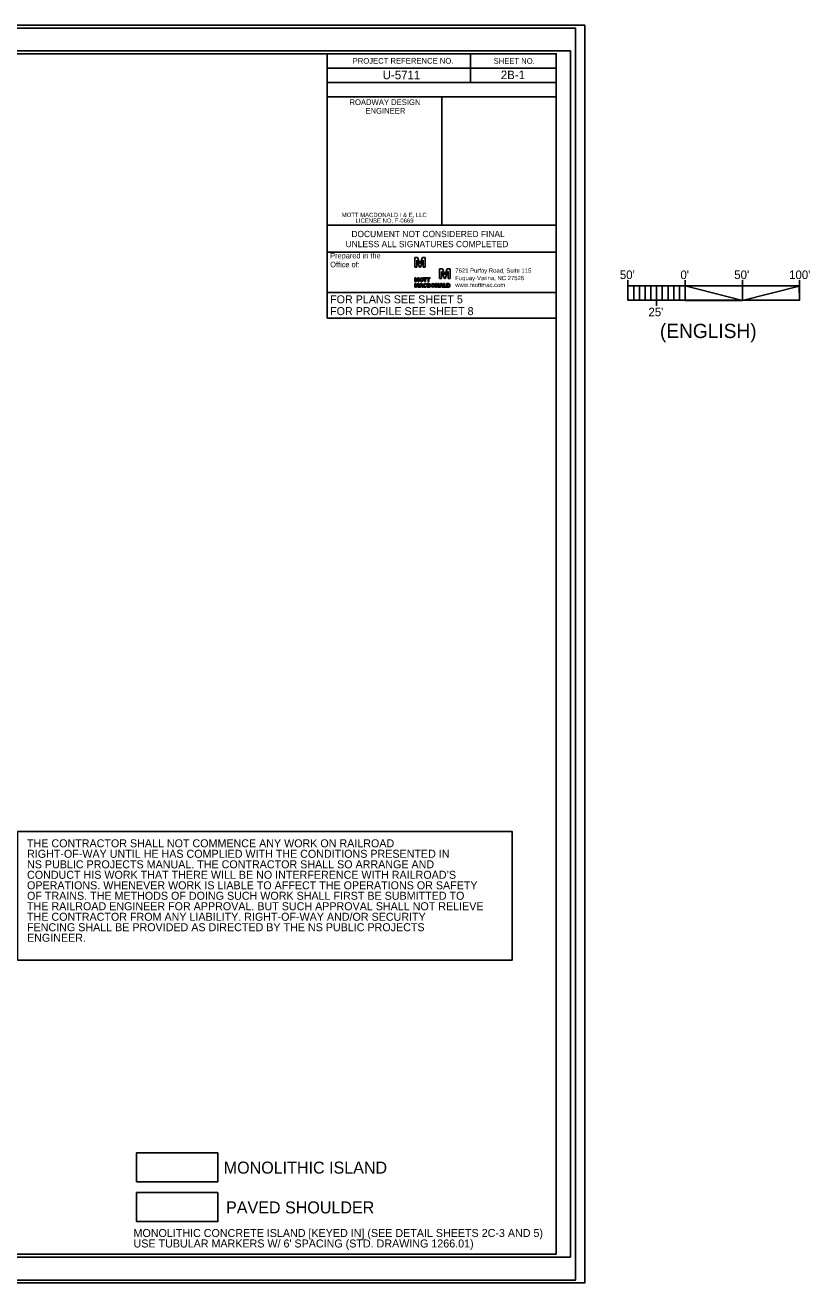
# Model space of a CAD drawing. Extents: x 1756964 to 1757438, y 736785 to 737067.
# Drawn here: x 1757266.4 to 1757437.8, y 736792 to 737067 of the extents above; entities that cross this region are included whole.
import ezdxf

# ---------------------------------------------------------------- set-up
doc = ezdxf.new("R2010")
doc.units = 0
for name, color, linetype in [('Old_Level_2', 7, 'Continuous'), ('Old_Level_40', 7, 'Continuous'), ('Old_Level_42', 7, 'Continuous'), ('Old_Level_45', 7, 'Continuous'), ('Old_Level_62', 7, 'Continuous'), ('Old_Level_63', 7, 'Continuous'), ('Prop Dimension', 7, 'Continuous'), ('Prop DSN Text', 7, 'Continuous'), ('Prop DSN White Annotation Label', 7, 'Continuous'), ('Prop PHM English Scale CELL', 7, 'Continuous'), ('Prop Shade Light', 7, 'Continuous'), ('Prop Shade Medium', 7, 'Continuous'), ('Sheet Data Field CELL', 7, 'Continuous'), ('Sheet Plan CELL', 7, 'Continuous'), ('Sheet Plot Border Inside CELL', 7, 'Continuous'), ('Sheet Plot Border Outside CELL', 7, 'Continuous'), ('Sheet Sticker Exception Certification CELL', 7, 'Continuous')]:
    doc.layers.add(name, color=color, linetype=linetype)

msp = doc.modelspace()

# ---------------------------------------------------------------- linework, layer by layer
at = {"layer": 'Old_Level_2'}
for p, q in [((1757352.13, 737016.21), (1757351.5, 737016.21)), ((1757351.5, 737016.21), (1757351.5, 737014.09)), ((1757351.95, 737014.09), (1757351.95, 737015.61)), ((1757351.95, 737015.61), (1757351.96, 737015.61)), ((1757351.96, 737015.61), (1757352.55, 737014.09)), ((1757352.64, 737014.9), (1757352.13, 737016.21)), ((1757352.64, 737014.88), (1757352.64, 737014.9)), ((1757352.66, 737014.88), (1757352.64, 737014.88)), ((1757353.17, 737016.21), (1757352.66, 737014.9)), ((1757352.66, 737014.9), (1757352.66, 737014.88)), ((1757352.75, 737014.09), (1757353.35, 737015.62)), ((1757353.8, 737016.21), (1757353.17, 737016.21)), ((1757353.35, 737015.62), (1757353.35, 737015.62)), ((1757353.35, 737015.62), (1757353.35, 737014.09)), ((1757353.8, 737014.09), (1757353.8, 737016.21)), ((1757351.5, 737014.09), (1757351.95, 737014.09)), ((1757352.55, 737014.09), (1757352.75, 737014.09)), ((1757353.35, 737014.09), (1757353.8, 737014.09)), ((1757357.53, 737013.74), (1757356.9, 737013.74)), ((1757356.9, 737013.74), (1757356.9, 737011.61)), ((1757357.35, 737011.61), (1757357.35, 737013.14)), ((1757357.35, 737013.14), (1757357.36, 737013.14)), ((1757357.36, 737013.14), (1757357.96, 737011.61)), ((1757358.05, 737012.42), (1757357.53, 737013.74)), ((1757358.05, 737012.4), (1757358.05, 737012.42)), ((1757358.06, 737012.4), (1757358.05, 737012.4)), ((1757358.57, 737013.74), (1757358.06, 737012.42)), ((1757358.06, 737012.42), (1757358.06, 737012.4)), ((1757358.15, 737011.61), (1757358.75, 737013.14)), ((1757359.2, 737013.74), (1757358.57, 737013.74)), ((1757358.75, 737013.14), (1757358.76, 737013.14)), ((1757358.76, 737013.14), (1757358.76, 737011.61)), ((1757359.2, 737011.61), (1757359.2, 737013.74)), ((1757351.74, 737011.76), (1757351.5, 737011.76)), ((1757351.5, 737011.76), (1757351.5, 737010.95)), ((1757351.5, 737010.95), (1757351.67, 737010.95)), ((1757351.74, 737010.5), (1757351.5, 737010.5)), ((1757351.5, 737010.5), (1757351.5, 737009.69)), ((1757351.5, 737009.69), (1757351.67, 737009.69)), ((1757351.67, 737010.95), (1757351.67, 737011.53)), ((1757351.67, 737011.53), (1757351.68, 737011.53)), ((1757351.67, 737011.53), (1757351.68, 737011.53)), ((1757351.67, 737009.69), (1757351.67, 737010.27)), ((1757351.67, 737010.27), (1757351.68, 737010.27)), ((1757351.68, 737011.53), (1757351.9, 737010.95)), ((1757351.68, 737010.27), (1757351.9, 737009.69)), ((1757351.94, 737011.25), (1757351.74, 737011.76)), ((1757351.94, 737009.99), (1757351.74, 737010.5)), ((1757351.9, 737010.95), (1757351.98, 737010.95)), ((1757351.9, 737009.69), (1757351.98, 737009.69)), ((1757352.14, 737011.76), (1757351.94, 737011.25)), ((1757352.14, 737010.5), (1757351.94, 737009.99)), ((1757351.98, 737010.95), (1757352.21, 737011.53)), ((1757351.98, 737009.69), (1757352.21, 737010.27)), ((1757352.38, 737011.76), (1757352.14, 737011.76)), ((1757352.38, 737010.5), (1757352.14, 737010.5)), ((1757352.21, 737011.53), (1757352.22, 737011.53)), ((1757352.21, 737011.53), (1757352.22, 737011.53)), ((1757352.21, 737011.53), (1757352.22, 737011.53)), ((1757352.21, 737010.27), (1757352.22, 737010.27)), ((1757352.22, 737011.53), (1757352.22, 737010.95)), ((1757352.22, 737010.95), (1757352.38, 737010.95)), ((1757352.22, 737010.27), (1757352.22, 737009.69)), ((1757352.22, 737009.69), (1757352.38, 737009.69)), ((1757352.38, 737010.95), (1757352.38, 737011.76)), ((1757352.38, 737010.95), (1757352.38, 737011.76)), ((1757352.38, 737009.69), (1757352.38, 737010.5)), ((1757354.09, 737009.85), (1757353.95, 737009.92)), ((1757354.09, 737009.85), (1757353.95, 737009.92)), ((1757353.97, 737010.23), (1757354.11, 737010.3)), ((1757353.97, 737010.23), (1757354.11, 737010.3)), ((1757354.59, 737010.5), (1757354.22, 737010.5)), ((1757354.22, 737010.5), (1757354.22, 737010.08)), ((1757354.22, 737010.08), (1757354.22, 737009.69)), ((1757354.22, 737009.69), (1757354.59, 737009.69)), ((1757354.39, 737009.84), (1757354.39, 737010.35)), ((1757354.39, 737010.35), (1757354.59, 737010.35)), ((1757354.59, 737009.84), (1757354.39, 737009.84)), ((1757356.9, 737011.61), (1757357.35, 737011.61)), ((1757357.96, 737011.61), (1757358.15, 737011.61)), ((1757358.43, 737010.5), (1757358.43, 737010.5)), ((1757358.8, 737010.5), (1757358.43, 737010.5)), ((1757358.43, 737010.5), (1757358.43, 737010.08)), ((1757358.43, 737010.08), (1757358.43, 737009.69)), ((1757358.43, 737009.69), (1757358.8, 737009.69)), ((1757358.6, 737009.84), (1757358.6, 737010.35)), ((1757358.6, 737010.35), (1757358.8, 737010.35)), ((1757358.8, 737009.84), (1757358.6, 737009.84)), ((1757358.76, 737011.61), (1757359.2, 737011.61)), ((1757358.8, 737010.34), (1757358.8, 737010.34))]:
    msp.add_line(p, q, dxfattribs=at)
for points in [[(1757352.48, 737009.69), (1757352.68, 737009.69), (1757352.73, 737009.82), (1757353.08, 737009.82), (1757353.13, 737009.69), (1757353.32, 737009.69), (1757353.01, 737010.5), (1757352.79, 737010.5), (1757352.48, 737009.69)], [(1757352.77, 737009.97), (1757352.9, 737010.32), (1757353.03, 737009.97), (1757352.77, 737009.97)], [(1757353.4, 737011.61), (1757353.64, 737011.61), (1757353.64, 737010.95), (1757353.81, 737010.95), (1757353.81, 737011.61), (1757354.05, 737011.61), (1757354.05, 737011.76), (1757353.4, 737011.76), (1757353.4, 737011.61)], [(1757354.15, 737011.61), (1757354.39, 737011.61), (1757354.39, 737010.95), (1757354.56, 737010.95), (1757354.56, 737011.61), (1757354.79, 737011.61), (1757354.79, 737011.76), (1757354.15, 737011.76), (1757354.15, 737011.61)], [(1757356.21, 737010.21), (1757356.22, 737010.21), (1757356.61, 737009.69), (1757356.77, 737009.69), (1757356.77, 737010.5), (1757356.6, 737010.5), (1757356.6, 737009.99), (1757356.22, 737010.5), (1757356.05, 737010.5), (1757356.05, 737009.69), (1757356.21, 737009.69), (1757356.21, 737010.21)], [(1757356.87, 737009.69), (1757357.07, 737009.69), (1757357.12, 737009.82), (1757357.47, 737009.82), (1757357.52, 737009.69), (1757357.71, 737009.69), (1757357.4, 737010.5), (1757357.19, 737010.5), (1757356.87, 737009.69)], [(1757357.17, 737009.97), (1757357.3, 737010.32), (1757357.43, 737009.97), (1757357.17, 737009.97)], [(1757358.33, 737009.69), (1757358.33, 737009.83), (1757357.98, 737009.83), (1757357.98, 737010.5), (1757357.81, 737010.5), (1757357.81, 737009.69), (1757358.33, 737009.69)], [(1757358.33, 737009.69), (1757358.33, 737009.83), (1757357.98, 737009.83), (1757357.98, 737010.5), (1757357.81, 737010.5), (1757357.81, 737009.69), (1757358.33, 737009.69), (1757358.33, 737009.83)]]:
    msp.add_lwpolyline(points, dxfattribs=at)
msp.add_arc((1757358.8, 737010.09), 0.406, 270, 90, dxfattribs=at)
for centre, major_axis, ratio in [((1757352.94, 737011.35), (0, 0.406), 0.993118), ((1757352.94, 737011.35), (0, 0.265), 0.916103), ((1757355.5, 737010.09), (0, 0.406), 0.993118), ((1757355.5, 737010.09), (0, 0.265), 0.916103)]:
    msp.add_ellipse(centre, major_axis=major_axis, ratio=ratio, dxfattribs=at)
for centre, major_axis, ratio, start_param, end_param in [((1757353.76, 737010.09), (0, 0.406), 0.993118, 5.246647, 10.366427), ((1757353.76, 737010.09), (0, 0.406), 0.993118, 5.246647, 10.366427), ((1757353.76, 737010.09), (0, 0.265), 0.916103, 5.276876, 9.424778), ((1757353.76, 737010.09), (0, 0.265), 0.916103, 5.276876, 10.296021), ((1757353.76, 737010.09), (0, 0.265), 0.916103, 3.141593, 4.012835), ((1757354.59, 737010.09), (0, -0.406), 0.930276, 0, 3.141593), ((1757354.59, 737010.1), (0, -0.253), 0.900832, 0, 3.141593), ((1757358.8, 737010.1), (0, -0.253), 0.900832, 0, 3.141593)]:
    msp.add_ellipse(centre, major_axis=major_axis, ratio=ratio, start_param=start_param, end_param=end_param, dxfattribs=at)
at = {"layer": 'Old_Level_40'}
for points in [[(1757308.47, 736820.45), (1757290.72, 736820.45), (1757290.72, 736814.1), (1757308.47, 736814.1)], [(1757308.47, 736811.75), (1757290.72, 736811.75), (1757290.72, 736805.4), (1757308.47, 736805.4)]]:
    msp.add_lwpolyline(points, close=True, dxfattribs=at)
at = {"layer": 'Old_Level_42'}
msp.add_lwpolyline([(1757382.4, 737008.54), (1757332.39, 737008.54), (1757332.39, 737017.36)], dxfattribs=at)
at = {"layer": 'Old_Level_62'}
msp.add_lwpolyline([(1756969.89, 736798.25), (1757382.39, 736798.25), (1757382.39, 737060.75), (1756969.89, 737060.75)], close=True, dxfattribs=at)
at = {"layer": 'Old_Level_63'}
msp.add_lwpolyline([(1757388.64, 737067), (1756963.64, 737067), (1756963.64, 736792), (1757388.64, 736792)], close=True, dxfattribs=at)
at = {"layer": 'Prop DSN Text'}
msp.add_lwpolyline([(1757332.39, 737008.54), (1757382.4, 737008.54), (1757382.4, 737002.92), (1757332.39, 737002.92)], close=True, dxfattribs=at)
at = {"layer": 'Prop DSN White Annotation Label'}
msp.add_lwpolyline([(1757264.72, 736890.67), (1757372.78, 736890.67), (1757372.78, 736862.56), (1757264.72, 736862.56)], close=True, dxfattribs=at)
at = {"layer": 'Prop PHM English Scale CELL'}
for p, q in [((1757398.08, 737011.48), (1757398.08, 737011.48)), ((1757398.08, 737011.23), (1757398.08, 737006.85)), ((1757435.58, 737009.98), (1757398.08, 737009.98)), ((1757398.08, 737009.98), (1757398.08, 737006.85)), ((1757404.33, 737009.98), (1757404.33, 737005.6)), ((1757410.58, 737011.23), (1757410.58, 737006.83)), ((1757423.08, 737011.48), (1757423.08, 737011.48)), ((1757423.08, 737011.23), (1757423.08, 737006.85)), ((1757435.58, 737011.48), (1757435.58, 737011.48)), ((1757435.58, 737011.23), (1757435.58, 737006.85)), ((1757435.58, 737006.85), (1757435.58, 737009.98)), ((1757398.08, 737006.85), (1757435.58, 737006.85))]:
    msp.add_line(p, q, dxfattribs=at)
for points in [[(1757399.33, 737009.98), (1757398.08, 737009.98), (1757398.08, 737006.85), (1757399.33, 737006.85)], [(1757400.58, 737009.98), (1757401.83, 737009.98), (1757401.83, 737006.85), (1757400.58, 737006.85)], [(1757403.08, 737009.98), (1757404.33, 737009.98), (1757404.33, 737006.85), (1757403.08, 737006.85)], [(1757405.58, 737009.98), (1757406.83, 737009.98), (1757406.83, 737006.85), (1757405.58, 737006.85)], [(1757408.08, 737009.98), (1757409.33, 737009.98), (1757409.33, 737006.85), (1757408.08, 737006.85)], [(1757410.58, 737009.98), (1757423.08, 737006.83), (1757410.58, 737006.83)], [(1757423.08, 737006.83), (1757435.52, 737009.93), (1757435.58, 737006.85)]]:
    msp.add_lwpolyline(points, close=True, dxfattribs=at)
at = {"layer": 'Prop Shade Light'}
msp.add_lwpolyline([(1757308.47, 736811.75), (1757290.72, 736811.75), (1757290.72, 736805.4), (1757308.47, 736805.4), (1757308.47, 736811.75)], dxfattribs=at)
at = {"layer": 'Prop Shade Medium'}
msp.add_lwpolyline([(1757308.47, 736820.45), (1757290.72, 736820.45), (1757290.72, 736814.1), (1757308.47, 736814.1), (1757308.47, 736820.45)], dxfattribs=at)
at = {"layer": 'Sheet Plan CELL'}
for p, q in [((1757363.64, 737060.73), (1757363.65, 737054.48)), ((1757332.38, 737057.61), (1757382.39, 737057.61)), ((1757332.38, 737054.48), (1757382.39, 737054.49)), ((1757332.38, 737054.48), (1757332.38, 737051.36)), ((1757357.39, 737051.36), (1757357.4, 737023.24))]:
    msp.add_line(p, q, dxfattribs=at)
for points in [[(1757382.4, 737060.75), (1757007.39, 737060.75), (1757007.39, 736798.25), (1757382.39, 736798.25)], [(1757332.38, 737060.75), (1757382.4, 737060.75), (1757382.39, 737054.49), (1757332.38, 737054.48)], [(1757332.38, 737051.36), (1757357.39, 737051.36), (1757357.39, 737023.23), (1757332.39, 737023.24)], [(1757357.39, 737051.36), (1757382.39, 737051.36), (1757382.39, 737023.23), (1757357.39, 737023.23)]]:
    msp.add_lwpolyline(points, close=True, dxfattribs=at)
at = {"layer": 'Sheet Plot Border Inside CELL'}
msp.add_lwpolyline([(1756969.02, 736797.62), (1757385.52, 736797.62), (1757385.52, 737061.37), (1756969.02, 737061.37)], close=True, dxfattribs=at)
at = {"layer": 'Sheet Plot Border Outside CELL'}
msp.add_lwpolyline([(1756965.77, 736792.62), (1757386.64, 736792.62), (1757386.64, 737066.37), (1756965.77, 737066.37)], close=True, dxfattribs=at)
at = {"layer": 'Sheet Sticker Exception Certification CELL'}
for p, q in [((1757332.39, 737017.36), (1757332.39, 737023.24)), ((1757332.39, 737023.24), (1757382.39, 737023.24)), ((1757382.39, 737023.23), (1757382.39, 737017.36)), ((1757382.39, 737017.36), (1757332.39, 737017.36))]:
    msp.add_line(p, q, dxfattribs=at)

# ---------------------------------------------------------------- texts
at = {"layer": 'Old_Level_2'}
for s, height, p in [('Office of:', 1.205, (1757333.02, 737014.05)), ('Prepared in the ', 1.2046, (1757333.02, 737015.99)), ('7621 Purfoy Road, Suite 115', 0.9375, (1757360.35, 737012.86)), ('Fuquay-Varina, NC 27526', 0.9375, (1757360.35, 737011.24)), ('www.mottmac.com', 0.9375, (1757360.35, 737009.72))]:
    msp.add_text(s, height=height, rotation=360, dxfattribs=at).set_placement(p)
at = {"layer": 'Old_Level_45'}
for s, p in [('MOTT MACDONALD I & E, LLC', (1757335.55, 737025.04)), (' LICENSE NO. F-0669', (1757338.21, 737023.79))]:
    msp.add_text(s, height=0.9375, rotation=0.0001, dxfattribs=at).set_placement(p)
at = {"layer": 'Prop Dimension'}
for s, p in [('MONOLITHIC CONCRETE ISLAND [KEYED IN] (SEE DETAIL SHEETS 2C-3 AND 5)', (1757290.05, 736802.02)), ("USE TUBULAR MARKERS W/ 6' SPACING (STD. DRAWING 1266.01)", (1757290.05, 736799.73))]:
    msp.add_text(s, height=1.75, rotation=360, dxfattribs=at).set_placement(p)
at = {"layer": 'Prop DSN Text'}
for s, height, rotation, p in [('FOR PLANS SEE SHEET 5', 1.75, 359.9997, (1757333, 737006.18)), ('FOR PROFILE SEE SHEET 8', 1.75, 359.9997, (1757333, 737003.6)), ('MONOLITHIC ISLAND', 2.625, 360, (1757309.76, 736815.88)), ('PAVED SHOULDER', 2.625, 360, (1757310.27, 736807.18))]:
    msp.add_text(s, height=height, rotation=rotation, dxfattribs=at).set_placement(p)
at = {"layer": 'Prop DSN White Annotation Label'}
for s, p in [('THE CONTRACTOR SHALL NOT COMMENCE ANY WORK ON RAILROAD ', (1757266.78, 736887.23)), ('RIGHT-OF-WAY UNTIL HE HAS COMPLIED WITH THE CONDITIONS PRESENTED IN ', (1757266.78, 736884.94)), ('NS PUBLIC PROJECTS MANUAL. THE CONTRACTOR SHALL SO ARRANGE AND ', (1757266.78, 736882.64)), ('OPERATIONS. WHENEVER WORK IS LIABLE TO AFFECT THE OPERATIONS OR SAFETY ', (1757266.78, 736878.05)), ('CONDUCT HIS WORK THAT THERE WILL BE NO INTERFERENCE WITH RAILROAD’S ', (1757266.78, 736880.35)), ('OF TRAINS. THE METHODS OF DOING SUCH WORK SHALL FIRST BE SUBMITTED TO ', (1757266.78, 736875.76)), ('THE RAILROAD ENGINEER FOR APPROVAL. BUT SUCH APPROVAL SHALL NOT RELIEVE ', (1757266.78, 736873.47)), ('THE CONTRACTOR FROM ANY LIABILITY. RIGHT-OF-WAY AND/OR SECURITY ', (1757266.78, 736871.17)), ('FENCING SHALL BE PROVIDED AS DIRECTED BY THE NS PUBLIC PROJECTS ', (1757266.78, 736868.88)), ('ENGINEER.', (1757266.78, 736866.58))]:
    msp.add_text(s, height=1.75, rotation=360, dxfattribs=at).set_placement(p)
at = {"layer": 'Prop PHM English Scale CELL'}
for s, height, p in [("50'", 1.875, (1757396.3, 737011.48)), ("0'", 1.875, (1757409.54, 737011.48)), ("50'", 1.875, (1757421.3, 737011.48)), ("100'", 1.875, (1757433.28, 737011.48)), ("25'", 1.875, (1757402.55, 737003.34)), ('(ENGLISH)', 3.125, (1757405.06, 736998.58))]:
    msp.add_text(s, height=height, rotation=360, dxfattribs=at).set_placement(p)
at = {"layer": 'Sheet Data Field CELL'}
for s, p in [('U-5711', (1757344.48, 737055.17)), ('2B-1', (1757370.29, 737055.19))]:
    msp.add_text(s, height=1.875, rotation=360, dxfattribs=at).set_placement(p)
at = {"layer": 'Sheet Plan CELL'}
for s, p in [('PROJECT REFERENCE NO.', (1757337.93, 737058.57)), ('SHEET NO.', (1757368.72, 737058.54)), ('ROADWAY DESIGN', (1757337.23, 737049.53)), ('ENGINEER', (1757340.72, 737047.65))]:
    msp.add_text(s, height=1.25, rotation=360, dxfattribs=at).set_placement(p)
at = {"layer": 'Sheet Sticker Exception Certification CELL'}
for s, p in [('DOCUMENT NOT CONSIDERED FINAL', (1757337.65, 737020.65)), ('UNLESS ALL SIGNATURES COMPLETED', (1757336.39, 737018.45))]:
    msp.add_text(s, height=1.375, rotation=360, dxfattribs=at).set_placement(p)

doc.saveas('drawing.dxf')
